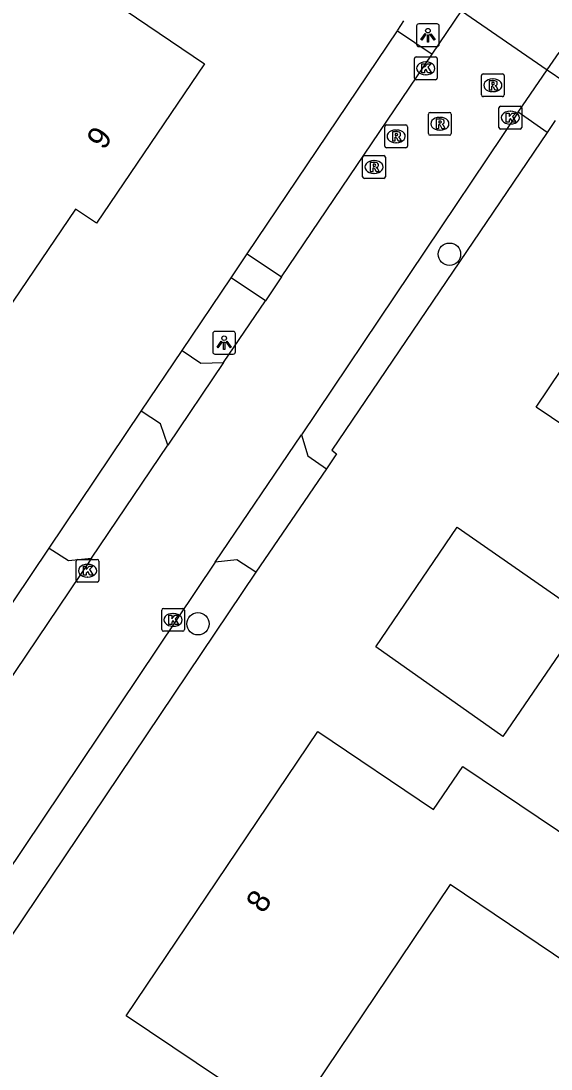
# Model space of a CAD drawing. Extents: x 163863 to 164644, y 379566 to 382155.
# Drawn here: x 164174.78 to 164198.04, y 381807.43 to 381853.41 of the extents above; entities that cross this region are included whole.
import ezdxf

# ---------------------------------------------------------------- set-up
doc = ezdxf.new("R2010")
doc.units = 0
for name, color, linetype in [('IMGEO_Boom', 7, 'Continuous'), ('IMGEO_Duiker', 7, 'Continuous'), ('IMGEO_Kolk', 7, 'Continuous'), ('IMGEO_Lichtpunt', 7, 'Continuous'), ('IMGEO_Pand', 7, 'Continuous'), ('IMGEO_Pand_nummerreeks', 7, 'Continuous'), ('IMGEO_Rijbaan_lokaal_open', 7, 'Continuous'), ('IMGEO_Rioolput', 7, 'Continuous'), ('IMGEO_Voetpad_halfverhard', 7, 'Continuous'), ('IMGEO_Voetpad_open', 7, 'Continuous')]:
    doc.layers.add(name, color=color, linetype=linetype)

msp = doc.modelspace()

# ---------------------------------------------------------------- linework, layer by layer
at = {"layer": 'IMGEO_Boom'}
for centre in [(164193.579, 381843.182), (164182.545, 381826.968)]:
    msp.add_circle(centre, 0.489, dxfattribs=at)
at = {"layer": 'IMGEO_Duiker'}
msp.add_lwpolyline([(164190.042, 381856.658), (164190.846, 381856.104), (164192.323, 381855.089), (164194.104, 381853.864), (164197.871, 381851.272), (164199.409, 381850.214), (164201.216, 381848.971), (164201.883, 381848.512)], dxfattribs=at)
at = {"layer": 'IMGEO_Kolk'}
for p, q in [((164192.04, 381850.909), (164192.04, 381851.761)), ((164192.115, 381851.835), (164192.967, 381851.835)), ((164192.528, 381851.615), (164192.553, 381851.615)), ((164193.041, 381851.761), (164193.041, 381850.909)), ((164192.551, 381851.055), (164192.526, 381851.055)), ((164192.967, 381850.835), (164192.115, 381850.835)), ((164195.825, 381849.672), (164196.677, 381849.672)), ((164195.75, 381848.746), (164195.75, 381849.598)), ((164196.238, 381849.452), (164196.263, 381849.452)), ((164196.751, 381849.598), (164196.751, 381848.746)), ((164196.261, 381848.892), (164196.236, 381848.892)), ((164196.677, 381848.672), (164195.825, 381848.672)), ((164177.203, 381828.869), (164177.203, 381829.721)), ((164177.278, 381829.795), (164178.13, 381829.795)), ((164177.691, 381829.575), (164177.716, 381829.575)), ((164178.204, 381829.721), (164178.204, 381828.869)), ((164177.714, 381829.015), (164177.689, 381829.015)), ((164178.13, 381828.795), (164177.278, 381828.795)), ((164181.029, 381827.641), (164181.881, 381827.641)), ((164180.954, 381826.715), (164180.954, 381827.567)), ((164181.442, 381827.421), (164181.467, 381827.421)), ((164181.955, 381827.567), (164181.955, 381826.715)), ((164181.465, 381826.861), (164181.44, 381826.861)), ((164181.881, 381826.641), (164181.029, 381826.641))]:
    msp.add_line(p, q, dxfattribs=at)
for points in [[(164192.04, 381850.909), (164192.04, 381851.761)], [(164192.115, 381851.835), (164192.967, 381851.835)], [(164192.361, 381851.535), (164192.484, 381851.535), (164192.484, 381851.384), (164192.614, 381851.535), (164192.778, 381851.535), (164192.632, 381851.384), (164192.785, 381851.135), (164192.633, 381851.135), (164192.548, 381851.299), (164192.484, 381851.232), (164192.484, 381851.135), (164192.361, 381851.135), (164192.361, 381851.535)], [(164193.041, 381851.761), (164193.041, 381850.909)], [(164192.967, 381850.835), (164192.115, 381850.835)], [(164195.825, 381849.672), (164196.677, 381849.672)], [(164195.75, 381848.746), (164195.75, 381849.598)], [(164196.071, 381849.372), (164196.194, 381849.372), (164196.194, 381849.221), (164196.324, 381849.372), (164196.488, 381849.372), (164196.342, 381849.221), (164196.495, 381848.972), (164196.343, 381848.972), (164196.258, 381849.136), (164196.194, 381849.069), (164196.194, 381848.972), (164196.071, 381848.972), (164196.071, 381849.372)], [(164196.751, 381849.598), (164196.751, 381848.746)], [(164196.677, 381848.672), (164195.825, 381848.672)], [(164177.203, 381828.869), (164177.203, 381829.721)], [(164177.278, 381829.795), (164178.13, 381829.795)], [(164177.524, 381829.495), (164177.647, 381829.495), (164177.647, 381829.344), (164177.777, 381829.495), (164177.941, 381829.495), (164177.795, 381829.344), (164177.948, 381829.095), (164177.796, 381829.095), (164177.711, 381829.259), (164177.647, 381829.192), (164177.647, 381829.095), (164177.524, 381829.095), (164177.524, 381829.495)], [(164178.204, 381829.721), (164178.204, 381828.869)], [(164178.13, 381828.795), (164177.278, 381828.795)], [(164181.029, 381827.641), (164181.881, 381827.641)], [(164180.954, 381826.715), (164180.954, 381827.567)], [(164181.275, 381827.341), (164181.398, 381827.341), (164181.398, 381827.19), (164181.528, 381827.341), (164181.692, 381827.341), (164181.546, 381827.19), (164181.699, 381826.941), (164181.547, 381826.941), (164181.462, 381827.105), (164181.398, 381827.038), (164181.398, 381826.941), (164181.275, 381826.941), (164181.275, 381827.341)], [(164181.955, 381827.567), (164181.955, 381826.715)], [(164181.881, 381826.641), (164181.029, 381826.641)]]:
    msp.add_lwpolyline(points, dxfattribs=at)
for centre, start, end in [((164192.117, 381851.759), 91.552, 178.448), ((164192.117, 381851.759), 91.552, 178.448), ((164192.965, 381851.759), 1.552, 88.448), ((164192.965, 381851.759), 1.552, 88.448), ((164192.117, 381850.911), 181.552, 268.448), ((164192.117, 381850.911), 181.552, 268.448), ((164192.965, 381850.911), 271.552, 358.448), ((164192.965, 381850.911), 271.552, 358.448), ((164195.827, 381849.596), 91.552, 178.448), ((164195.827, 381849.596), 91.552, 178.448), ((164196.675, 381849.596), 1.552, 88.448), ((164196.675, 381849.596), 1.552, 88.448), ((164195.827, 381848.748), 181.552, 268.448), ((164195.827, 381848.748), 181.552, 268.448), ((164196.675, 381848.748), 271.552, 358.448), ((164196.675, 381848.748), 271.552, 358.448), ((164177.28, 381829.719), 91.552, 178.448), ((164177.28, 381829.719), 91.552, 178.448), ((164178.128, 381829.719), 1.552, 88.448), ((164178.128, 381829.719), 1.552, 88.448), ((164177.28, 381828.871), 181.552, 268.448), ((164177.28, 381828.871), 181.552, 268.448), ((164178.128, 381828.871), 271.552, 358.448), ((164178.128, 381828.871), 271.552, 358.448), ((164181.031, 381827.565), 91.552, 178.448), ((164181.031, 381827.565), 91.552, 178.448), ((164181.879, 381827.565), 1.552, 88.448), ((164181.879, 381827.565), 1.552, 88.448), ((164181.031, 381826.717), 181.552, 268.448), ((164181.031, 381826.717), 181.552, 268.448), ((164181.879, 381826.717), 271.552, 358.448), ((164181.879, 381826.717), 271.552, 358.448)]:
    msp.add_arc(centre, 0.0765, start, end, dxfattribs=at)
for centre, major_axis, ratio, start_param, end_param in [((164192.527, 381851.335), (-0.387, 0.002), 0.722429, 4.712389, 7.853982), ((164192.552, 381851.335), (-0.39, 0.002), 0.717154, 1.570796, 4.712389), ((164196.237, 381849.172), (-0.387, 0.002), 0.722429, 4.712389, 7.853982), ((164196.262, 381849.172), (-0.39, 0.002), 0.717154, 1.570796, 4.712389), ((164177.69, 381829.295), (-0.387, 0.002), 0.722429, 4.712389, 7.853982), ((164177.715, 381829.295), (-0.39, 0.002), 0.717154, 1.570796, 4.712389), ((164181.441, 381827.141), (-0.387, 0.002), 0.722429, 4.712389, 7.853982), ((164181.466, 381827.141), (-0.39, 0.002), 0.717154, 1.570796, 4.712389)]:
    msp.add_ellipse(centre, major_axis=major_axis, ratio=ratio, start_param=start_param, end_param=end_param, dxfattribs=at)
at = {"layer": 'IMGEO_Lichtpunt'}
for p, q in [((164192.135, 381853.193), (164192.135, 381852.386)), ((164192.135, 381853.193), (164192.135, 381852.386)), ((164193.037, 381853.288), (164192.229, 381853.288)), ((164193.037, 381853.288), (164192.229, 381853.288)), ((164193.131, 381852.386), (164193.131, 381853.193)), ((164193.131, 381852.386), (164193.131, 381853.193)), ((164192.229, 381852.292), (164193.037, 381852.292)), ((164192.229, 381852.292), (164193.037, 381852.292)), ((164183.195, 381839.7), (164183.195, 381838.893)), ((164183.195, 381839.7), (164183.195, 381838.893)), ((164184.097, 381839.795), (164183.289, 381839.795)), ((164184.097, 381839.795), (164183.289, 381839.795)), ((164184.191, 381838.893), (164184.191, 381839.7)), ((164184.191, 381838.893), (164184.191, 381839.7)), ((164183.289, 381838.799), (164184.097, 381838.799)), ((164183.289, 381838.799), (164184.097, 381838.799))]:
    msp.add_line(p, q, dxfattribs=at)
for points in [[(164192.509, 381852.857), (164192.548, 381852.829), (164192.36, 381852.567), (164192.322, 381852.594), (164192.509, 381852.857)], [(164192.611, 381852.809), (164192.658, 381852.809), (164192.658, 381852.487), (164192.611, 381852.487), (164192.611, 381852.809)], [(164192.721, 381852.829), (164192.759, 381852.856), (164192.946, 381852.594), (164192.907, 381852.566), (164192.721, 381852.829)], [(164183.569, 381839.364), (164183.608, 381839.336), (164183.42, 381839.074), (164183.382, 381839.101), (164183.569, 381839.364)], [(164183.671, 381839.316), (164183.718, 381839.316), (164183.718, 381838.994), (164183.671, 381838.994), (164183.671, 381839.316)], [(164183.781, 381839.336), (164183.819, 381839.363), (164184.006, 381839.101), (164183.967, 381839.073), (164183.781, 381839.336)]]:
    msp.add_lwpolyline(points, dxfattribs=at)
for centre in [(164192.634, 381852.991), (164183.694, 381839.498)]:
    msp.add_circle(centre, 0.0994, dxfattribs=at)
for centre, start, end in [((164192.229, 381853.193), 90, 180), ((164192.229, 381853.193), 90, 180), ((164193.037, 381853.193), 0, 90), ((164193.037, 381853.193), 0, 90), ((164192.229, 381852.386), 180, 270), ((164192.229, 381852.386), 180, 270), ((164193.037, 381852.386), 270, 0), ((164193.037, 381852.386), 270, 360), ((164183.289, 381839.7), 90, 180), ((164183.289, 381839.7), 90, 180), ((164184.097, 381839.7), 0, 90), ((164184.097, 381839.7), 0, 90), ((164183.289, 381838.893), 180, 270), ((164183.289, 381838.893), 180, 270), ((164184.097, 381838.893), 270, 0), ((164184.097, 381838.893), 270, 360)]:
    msp.add_arc(centre, 0.0946, start, end, dxfattribs=at)
at = {"layer": 'IMGEO_Pand'}
for points in [[(164174.878, 381856.933), (164182.827, 381851.535), (164178.088, 381844.548), (164177.173, 381845.157), (164173.526, 381839.8), (164167.892, 381843.609), (164171.538, 381849.002), (164168.319, 381851.178)], [(164197.39, 381836.467), (164201.794, 381843.035), (164208.819, 381838.297), (164215.56, 381833.752), (164211.149, 381827.193), (164197.39, 381836.467)], [(164190.351, 381825.963), (164193.911, 381831.206), (164199.528, 381827.3), (164195.916, 381822.029), (164190.351, 381825.963)], [(164179.403, 381809.776), (164187.804, 381822.239), (164192.882, 381818.816), (164194.165, 381820.708), (164206.574, 381812.36), (164205.701, 381811.062), (164201.779, 381813.699), (164200.08, 381811.174), (164193.606, 381815.529), (164186.515, 381804.988), (164179.403, 381809.776)]]:
    msp.add_lwpolyline(points, dxfattribs=at)
at = {"layer": 'IMGEO_Rijbaan_lokaal_open'}
for points in [[(164192.817, 381851.959), (164194.104, 381853.864), (164194.609, 381854.612)], [(164186.204, 381842.193), (164192.817, 381851.959)], [(164196.592, 381849.406), (164197.871, 381851.272), (164198.396, 381852.037)], [(164196.592, 381849.406), (164187.087, 381835.261)], [(164186.204, 381842.193), (164185.505, 381841.141)], [(164183.67, 381838.426), (164185.505, 381841.141)], [(164180.059, 381836.297), (164181.855, 381838.961)], [(164181.855, 381838.961), (164182.674, 381838.407), (164183.67, 381838.426)], [(164183.67, 381838.426), (164181.218, 381834.798)], [(164181.218, 381834.798), (164180.897, 381835.736), (164180.059, 381836.297)], [(164183.294, 381829.671), (164187.087, 381835.261)], [(164187.087, 381835.261), (164187.373, 381834.333), (164188.179, 381833.768)], [(164177.875, 381829.852), (164181.218, 381834.798)], [(164188.179, 381833.768), (164185.088, 381829.228)], [(164172.905, 381825.67), (164176.013, 381830.292)], [(164176.013, 381830.292), (164176.867, 381829.747), (164177.875, 381829.852)], [(164183.294, 381829.671), (164168.994, 381808.366)], [(164177.875, 381829.852), (164174.051, 381824.163)], [(164185.088, 381829.228), (164184.248, 381829.772), (164183.294, 381829.671)]]:
    msp.add_lwpolyline(points, dxfattribs=at)
at = {"layer": 'IMGEO_Rioolput'}
for p, q in [((164195.057, 381851.093), (164195.909, 381851.093)), ((164194.982, 381850.167), (164194.982, 381851.019)), ((164195.47, 381850.873), (164195.495, 381850.873)), ((164195.983, 381851.019), (164195.983, 381850.167)), ((164195.493, 381850.313), (164195.468, 381850.313)), ((164195.909, 381850.093), (164195.057, 381850.093)), ((164192.657, 381848.477), (164192.657, 381849.329)), ((164192.732, 381849.403), (164193.584, 381849.403)), ((164193.658, 381849.329), (164193.658, 381848.477)), ((164190.74, 381847.924), (164190.74, 381848.776)), ((164190.815, 381848.85), (164191.667, 381848.85)), ((164191.741, 381848.776), (164191.741, 381847.924)), ((164193.145, 381849.183), (164193.17, 381849.183)), ((164191.228, 381848.63), (164191.253, 381848.63)), ((164193.584, 381848.403), (164192.732, 381848.403)), ((164193.168, 381848.623), (164193.143, 381848.623)), ((164191.667, 381847.85), (164190.815, 381847.85)), ((164191.251, 381848.07), (164191.226, 381848.07)), ((164189.77, 381846.58), (164189.77, 381847.432)), ((164189.845, 381847.506), (164190.697, 381847.506)), ((164190.771, 381847.432), (164190.771, 381846.58)), ((164190.258, 381847.286), (164190.283, 381847.286)), ((164190.697, 381846.506), (164189.845, 381846.506)), ((164190.281, 381846.726), (164190.256, 381846.726))]:
    msp.add_line(p, q, dxfattribs=at)
for points in [[(164195.057, 381851.093), (164195.909, 381851.093)], [(164194.982, 381850.167), (164194.982, 381851.019)], [(164195.571, 381850.791), (164195.319, 381850.793), (164195.319, 381850.393)], [(164195.497, 381850.712), (164195.443, 381850.712), (164195.443, 381850.631)], [(164195.443, 381850.631), (164195.495, 381850.631)], [(164195.983, 381851.019), (164195.983, 381850.167)], [(164195.319, 381850.393), (164195.443, 381850.393), (164195.443, 381850.555), (164195.454, 381850.555)], [(164195.501, 381850.526), (164195.572, 381850.393), (164195.712, 381850.393), (164195.647, 381850.519)], [(164195.909, 381850.093), (164195.057, 381850.093)], [(164192.657, 381848.477), (164192.657, 381849.329)], [(164192.732, 381849.403), (164193.584, 381849.403)], [(164193.658, 381849.329), (164193.658, 381848.477)], [(164190.74, 381847.924), (164190.74, 381848.776)], [(164190.815, 381848.85), (164191.667, 381848.85)], [(164191.741, 381848.776), (164191.741, 381847.924)], [(164193.246, 381849.101), (164192.994, 381849.103), (164192.994, 381848.703)], [(164192.994, 381848.703), (164193.118, 381848.703), (164193.118, 381848.865), (164193.129, 381848.865)], [(164193.172, 381849.022), (164193.118, 381849.022), (164193.118, 381848.941)], [(164193.118, 381848.941), (164193.17, 381848.941)], [(164193.176, 381848.836), (164193.247, 381848.703), (164193.387, 381848.703), (164193.322, 381848.829)], [(164191.329, 381848.548), (164191.077, 381848.55), (164191.077, 381848.15)], [(164191.077, 381848.15), (164191.201, 381848.15), (164191.201, 381848.312), (164191.212, 381848.312)], [(164191.255, 381848.469), (164191.201, 381848.469), (164191.201, 381848.388)], [(164191.201, 381848.388), (164191.253, 381848.388)], [(164191.259, 381848.283), (164191.33, 381848.15), (164191.47, 381848.15), (164191.405, 381848.276)], [(164193.584, 381848.403), (164192.732, 381848.403)], [(164191.667, 381847.85), (164190.815, 381847.85)], [(164189.77, 381846.58), (164189.77, 381847.432)], [(164189.845, 381847.506), (164190.697, 381847.506)], [(164190.771, 381847.432), (164190.771, 381846.58)], [(164190.359, 381847.204), (164190.107, 381847.206), (164190.107, 381846.806)], [(164190.107, 381846.806), (164190.231, 381846.806), (164190.231, 381846.968), (164190.242, 381846.968)], [(164190.285, 381847.125), (164190.231, 381847.125), (164190.231, 381847.044)], [(164190.231, 381847.044), (164190.283, 381847.044)], [(164190.289, 381846.939), (164190.36, 381846.806), (164190.5, 381846.806), (164190.435, 381846.932)], [(164190.697, 381846.506), (164189.845, 381846.506)]]:
    msp.add_lwpolyline(points, dxfattribs=at)
for centre, radius, start, end in [((164195.059, 381851.017), 0.0765, 91.552, 178.448), ((164195.059, 381851.017), 0.0765, 91.552, 178.448), ((164195.907, 381851.017), 0.0765, 1.552, 88.448), ((164195.907, 381851.017), 0.0765, 1.552, 88.448), ((164195.479, 381850.82), 0.19, 274.7715, 282.9687), ((164195.503, 381850.616), 0.0964, 77.0061, 93.1865), ((164195.517, 381850.673), 0.0378, 276.6634, 79.6772), ((164195.57, 381850.681), 0.109, 350.3612, 89.416), ((164195.568, 381850.681), 0.112, 277.5842, 350.9817), ((164195.059, 381850.169), 0.0765, 181.552, 268.448), ((164195.059, 381850.169), 0.0765, 181.552, 268.448), ((164195.453, 381850.502), 0.0533, 26.0293, 88.6989), ((164195.552, 381850.466), 0.108, 29.5134, 73.7905), ((164195.907, 381850.169), 0.0765, 271.552, 358.448), ((164195.907, 381850.169), 0.0765, 271.552, 358.448), ((164192.734, 381849.327), 0.0765, 91.552, 178.448), ((164192.734, 381849.327), 0.0765, 91.552, 178.448), ((164193.582, 381849.327), 0.0765, 1.552, 88.448), ((164193.582, 381849.327), 0.0765, 1.552, 88.448), ((164190.817, 381848.774), 0.0765, 91.552, 178.448), ((164190.817, 381848.774), 0.0765, 91.552, 178.448), ((164191.665, 381848.774), 0.0765, 1.552, 88.448), ((164191.665, 381848.774), 0.0765, 1.552, 88.448), ((164193.128, 381848.812), 0.0533, 26.0293, 88.6989), ((164193.154, 381849.13), 0.19, 274.7715, 282.9687), ((164193.178, 381848.926), 0.0964, 77.0061, 93.1865), ((164193.192, 381848.983), 0.0378, 276.6634, 79.6772), ((164193.245, 381848.991), 0.109, 350.3612, 89.416), ((164193.243, 381848.991), 0.112, 277.5842, 350.9817), ((164193.227, 381848.776), 0.108, 29.5134, 73.7905), ((164191.211, 381848.259), 0.0533, 26.0293, 88.6989), ((164191.237, 381848.577), 0.19, 274.7715, 282.9687), ((164191.261, 381848.373), 0.0964, 77.0061, 93.1865), ((164191.275, 381848.43), 0.0378, 276.6634, 79.6772), ((164191.328, 381848.438), 0.109, 350.3612, 89.416), ((164191.326, 381848.438), 0.112, 277.5842, 350.9817), ((164191.31, 381848.223), 0.108, 29.5134, 73.7905), ((164192.734, 381848.479), 0.0765, 181.552, 268.448), ((164192.734, 381848.479), 0.0765, 181.552, 268.448), ((164193.582, 381848.479), 0.0765, 271.552, 358.448), ((164193.582, 381848.479), 0.0765, 271.552, 358.448), ((164190.817, 381847.926), 0.0765, 181.552, 268.448), ((164190.817, 381847.926), 0.0765, 181.552, 268.448), ((164191.665, 381847.926), 0.0765, 271.552, 358.448), ((164191.665, 381847.926), 0.0765, 271.552, 358.448), ((164189.847, 381847.43), 0.0765, 91.552, 178.448), ((164189.847, 381847.43), 0.0765, 91.552, 178.448), ((164190.695, 381847.43), 0.0765, 1.552, 88.448), ((164190.695, 381847.43), 0.0765, 1.552, 88.448), ((164190.241, 381846.915), 0.0533, 26.0293, 88.6989), ((164190.267, 381847.233), 0.19, 274.7715, 282.9687), ((164190.291, 381847.029), 0.0964, 77.0061, 93.1865), ((164190.305, 381847.086), 0.0378, 276.6634, 79.6772), ((164190.358, 381847.094), 0.109, 350.3612, 89.416), ((164190.356, 381847.094), 0.112, 277.5842, 350.9817), ((164190.34, 381846.879), 0.108, 29.5134, 73.7905), ((164189.847, 381846.582), 0.0765, 181.552, 268.448), ((164189.847, 381846.582), 0.0765, 181.552, 268.448), ((164190.695, 381846.582), 0.0765, 271.552, 358.448), ((164190.695, 381846.582), 0.0765, 271.552, 358.448)]:
    msp.add_arc(centre, radius, start, end, dxfattribs=at)
for centre, major_axis, ratio, start_param, end_param in [((164195.469, 381850.593), (-0.387, 0.002), 0.722429, 4.712389, 7.853982), ((164195.494, 381850.593), (-0.39, 0.002), 0.717154, 1.570796, 4.712389), ((164193.144, 381848.903), (-0.387, 0.002), 0.722429, 4.712389, 7.853982), ((164193.169, 381848.903), (-0.39, 0.002), 0.717154, 1.570796, 4.712389), ((164191.227, 381848.35), (-0.387, 0.002), 0.722429, 4.712389, 7.853982), ((164191.252, 381848.35), (-0.39, 0.002), 0.717154, 1.570796, 4.712389), ((164190.257, 381847.006), (-0.387, 0.002), 0.722429, 4.712389, 7.853982), ((164190.282, 381847.006), (-0.39, 0.002), 0.717154, 1.570796, 4.712389)]:
    msp.add_ellipse(centre, major_axis=major_axis, ratio=ratio, start_param=start_param, end_param=end_param, dxfattribs=at)
at = {"layer": 'IMGEO_Voetpad_halfverhard'}
for points in [[(164184.705, 381843.191), (164191.306, 381852.987)], [(164197.859, 381848.521), (164188.424, 381834.578), (164188.626, 381834.431), (164188.179, 381833.768)], [(164181.855, 381838.961), (164183.999, 381842.144)], [(164176.013, 381830.292), (164180.059, 381836.297)], [(164185.088, 381829.228), (164165.885, 381800.687)]]:
    msp.add_lwpolyline(points, dxfattribs=at)
at = {"layer": 'IMGEO_Voetpad_open'}
for points in [[(164191.306, 381852.987), (164191.32, 381853.008), (164191.58, 381853.421)], [(164191.306, 381852.987), (164192.817, 381851.959)], [(164197.859, 381848.521), (164196.592, 381849.406)], [(164198.212, 381849.047), (164197.859, 381848.521)], [(164183.999, 381842.144), (164184.705, 381843.191)], [(164184.705, 381843.191), (164186.204, 381842.193)], [(164185.505, 381841.141), (164183.999, 381842.144)]]:
    msp.add_lwpolyline(points, dxfattribs=at)

# ---------------------------------------------------------------- texts
at = {"layer": 'IMGEO_Pand_nummerreeks'}
for s, rotation, p in [('9', 55.8519, (164178.42, 381847.709)), ('8', 56.0181, (164185.413, 381814.22))]:
    msp.add_text(s, height=1, rotation=rotation, dxfattribs=at).set_placement(p)

doc.saveas('drawing.dxf')
